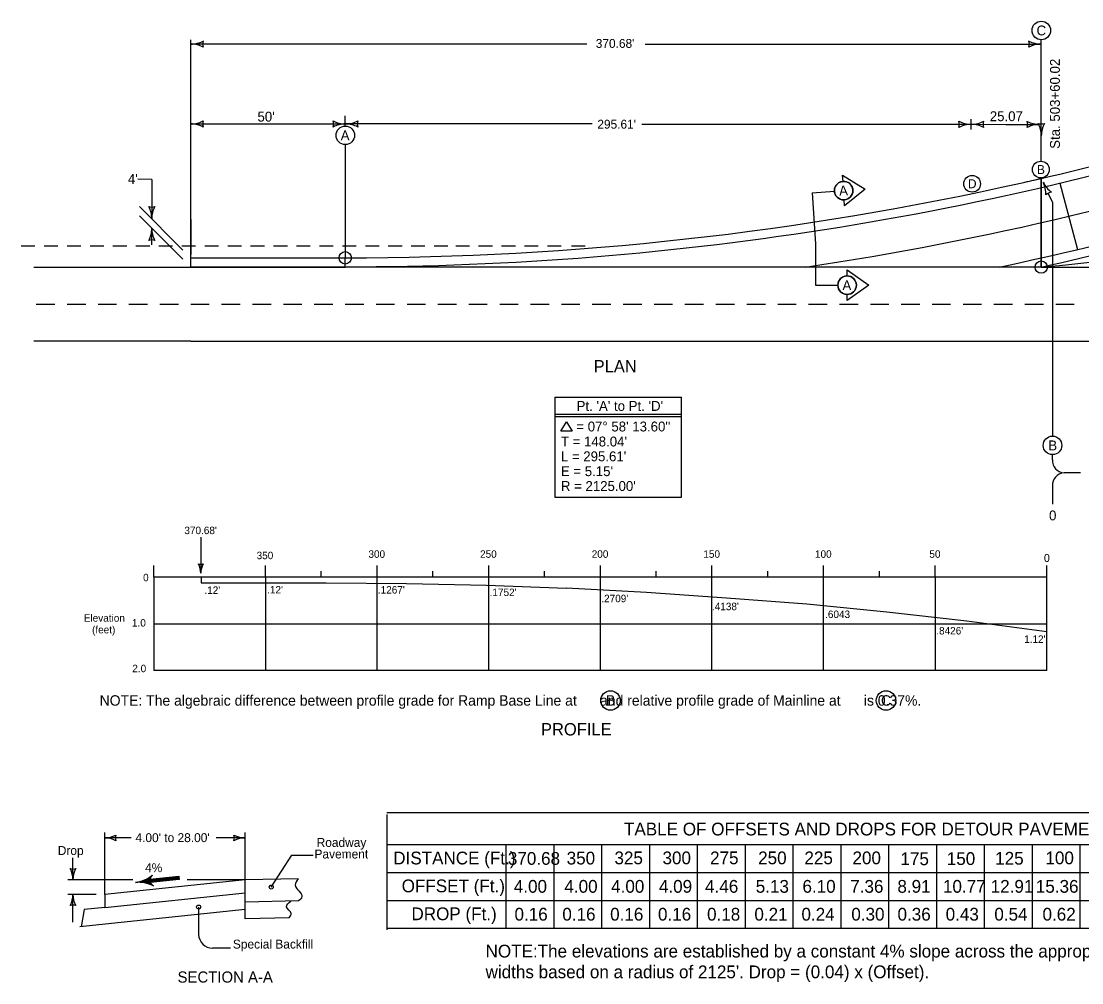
# Model space of a CAD drawing. Extents: x 10133 to 81668, y 4099 to 11018.
# Drawn here: x 10200 to 12089, y 4167 to 5879 of the extents above; entities that cross this region are included whole.
import ezdxf

# ---------------------------------------------------------------- set-up
doc = ezdxf.new("R2010")
doc.units = 0
for name, color, linetype in [('Default', 7, 'Continuous'), ('dsnCellElements', 7, 'Continuous'), ('Level 10', 7, 'Continuous'), ('Level 12', 7, 'Continuous'), ('Level 4', 7, 'Continuous'), ('Level 5', 7, 'Continuous'), ('SheetAddendum', 7, 'Continuous'), ('ShtPlotIdentification', 7, 'Continuous')]:
    doc.layers.add(name, color=color, linetype=linetype)

msp = doc.modelspace()

# ---------------------------------------------------------------- linework, layer by layer
at = {"layer": 'Default'}
for p, q in [((12016.5, 5441.5), (12016.5, 5599.5)), ((12016.5, 5599.5), (12016.5, 5441.5)), ((12049.8, 5590.9), (12080.7, 5472.7)), ((10488, 5471.9), (10410.7, 5549.2)), ((10488, 5455.4), (10410.7, 5532.7)), ((12016.5, 5441.5), (10501.9, 5441.5)), ((12016.5, 5441.5), (10501.9, 5441.5)), ((10776.9, 5441.5), (10776.9, 5458))]:
    msp.add_line(p, q, dxfattribs=at)
for points in [[(10501.9, 5441.5), (10501.9, 5458)], [(10501.9, 5458), (10776.9, 5458)]]:
    msp.add_lwpolyline(points, dxfattribs=at)
for centre, radius, start, end in [((10776.9, 10959.1), 5517, 270, 288.3725), ((10776.9, 10959.1), 5501.1, 282.6618, 288.3725), ((10776.9, 10959.1), 5578, 278.4444, 288.3725), ((10776.9, 10959.1), 5501.1, 270, 282.6618), ((10776.9, 10959.1), 5501.1, 270, 282.6618), ((10776.9, 10959.1), 5639.1, 281.9188, 288.3725), ((10776.9, 10959.1), 5501.1, 282.6618, 283.0225), ((10776.9, 10959.1), 5655.1, 282.6618, 288.3725), ((11515.8, 10985.3), 5566.3, 275.1605, 280.5457)]:
    msp.add_arc(centre, radius, start, end, dxfattribs=at)
at = {"layer": 'dsnCellElements'}
for p, q in [((12425.9, 4469.7), (10851.2, 4469.7)), ((10851.2, 4467.2), (10851.2, 4261.4)), ((12425.9, 4412.9), (10851.2, 4412.9)), ((11063.2, 4412.9), (11063.2, 4263.9)), ((11148.4, 4412.9), (11148.4, 4412.9)), ((11148.4, 4412.9), (11148.4, 4263.9)), ((11148.6, 4412.9), (11148.6, 4412.9)), ((11148.8, 4412.9), (11148.8, 4412.9)), ((11149.1, 4412.9), (11149.1, 4412.9)), ((11233.6, 4412.9), (11233.6, 4263.9)), ((11233.6, 4412.9), (11233.6, 4412.9)), ((11233.6, 4412.9), (11233.6, 4263.9)), ((11233.8, 4412.9), (11233.8, 4412.9)), ((11234, 4412.9), (11234, 4412.9)), ((11234.2, 4412.9), (11234.2, 4412.9)), ((11318.7, 4412.9), (11318.7, 4263.9)), ((11403.9, 4412.9), (11403.9, 4263.9)), ((11489.1, 4412.9), (11489.1, 4263.9)), ((11574.2, 4412.9), (11574.2, 4263.9)), ((11659.4, 4412.9), (11659.4, 4263.9)), ((11744.6, 4412.9), (11744.6, 4263.9)), ((11829.7, 4412.9), (11829.7, 4263.9)), ((11914.9, 4412.9), (11914.9, 4263.9)), ((12000.1, 4412.9), (12000.1, 4263.9)), ((12085.3, 4412.9), (12085.3, 4263.9)), ((12425.9, 4363.2), (10851.2, 4363.2)), ((12425.9, 4313.5), (10851.2, 4313.5)), ((12425.9, 4263.9), (10851.2, 4263.9))]:
    msp.add_line(p, q, dxfattribs=at)
at = {"layer": 'Level 10'}
for p, q in [((12036.5, 5557.3), (12029, 5573.1)), ((12036.5, 5557.3), (12036.5, 5140.6)), ((11150, 5209.9), (11150, 5031.8)), ((11150, 5209.9), (11375.5, 5209.9)), ((11375.5, 5031.8), (11375.5, 5209.9)), ((11150, 5179.9), (11375.5, 5179.9)), ((11150, 5175.7), (11375.5, 5175.7)), ((11161, 5149.4), (11170.9, 5165.9)), ((11170.9, 5165.9), (11180.8, 5149.4)), ((11180.8, 5149.4), (11161, 5149.4)), ((12036.5, 5098.4), (12036.5, 5107.6)), ((12086.5, 5075.2), (12057, 5075.2)), ((12036.5, 5052), (12036.5, 5019.3)), ((11150, 5031.8), (11375.5, 5031.8)), ((10348.6, 4324.7), (10348.6, 4434.9)), ((10598.7, 4350.8), (10598.7, 4434.9)), ((10515.9, 4302.2), (10515.9, 4253.8)), ((10572.4, 4229), (10540.7, 4229))]:
    msp.add_line(p, q, dxfattribs=at)
for centre, radius in [((12016.5, 5862.8), 16.5), ((10777.1, 5676.1), 16.5), ((12015.7, 5615.2), 14.9), ((11893.3, 5589.9), 14.9), ((10776.9, 5458), 11), ((12016.5, 5441.5), 11), ((12036.5, 5124.1), 16.5)]:
    msp.add_circle(centre, radius, dxfattribs=at)
for centre, radius, start, end in [((12016.5, 5714.6), 18.1, 252.2666, 287.7334), ((11969.7, 5675.4), 46.8, 0, 28.0725), ((12063.3, 5675.4), 46.8, 151.9275, 180), ((11977.3, 5572.1), 47.3, 357.3748, 25.4473), ((12062.8, 5612.8), 47.3, 205.4473, 233.5198), ((12037.1, 5556.6), 18.3, 97.714, 133.1807), ((10432.5, 5566.6), 18.1, 252.2666, 287.7334), ((10385.7, 5527.4), 46.8, 0, 28.0725), ((10479.2, 5527.4), 46.8, 151.9275, 180), ((10385.7, 5510.9), 46.8, 331.9275, 0), ((10479.2, 5510.9), 46.8, 180, 208.0725), ((10432.5, 5471.7), 18.1, 72.2667, 107.7334), ((12058.5, 5097.1), 22, 176.7081, 265.9437), ((12058.5, 5053.3), 22, 94.0563, 183.2919), ((10540.7, 4253.8), 24.8, 180, 270)]:
    msp.add_arc(centre, radius, start, end, dxfattribs=at)
for centre, major_axis, start_param, end_param in [((10519.7, 4926), (0, -13.6), 5.97368, 6.592691), ((10485.9, 4896.4), (0, 35.3), 4.712389, 5.202346), ((10553.5, 4896.4), (0, -35.3), 4.222432, 4.712389)]:
    msp.add_ellipse(centre, major_axis=major_axis, ratio=0.956827, start_param=start_param, end_param=end_param, dxfattribs=at)
at = {"layer": 'Level 12'}
for centre in [(10645.2, 4337.8), (10515.9, 4302.2)]:
    msp.add_circle(centre, 3.52, dxfattribs=at)
at = {"layer": 'Level 4'}
for p, q in [((11608.5, 5574), (11648, 5576.6)), ((11608.5, 5574), (11614.6, 5483.1)), ((11614.6, 5483.1), (11614.6, 5409.3)), ((11614.6, 5409.3), (11654.2, 5409.3))]:
    msp.add_line(p, q, dxfattribs=at)
for points in [[(11663.4, 5594.2), (11662.7, 5605.1), (11702.9, 5580.3), (11666.3, 5550.3), (11665.6, 5561.2)], [(11663.4, 5594.2), (11663.4, 5594.2), (11663.4, 5594.2)], [(11670.7, 5425.8), (11670.7, 5436.8), (11709.2, 5409.3), (11670.7, 5381.8), (11670.7, 5392.8)], [(11670.7, 5425.8), (11670.7, 5425.8), (11670.7, 5425.8)]]:
    msp.add_lwpolyline(points, dxfattribs=at)
for centre, radius in [((11664.5, 5577.7), 16.5), ((11670.7, 5409.3), 16.5), ((11249.3, 4669.9), 17.4), ((11740, 4669.9), 17.4)]:
    msp.add_circle(centre, radius, dxfattribs=at)
for centre, start, end in [((11664.5, 5577.7), 93.8133, 273.815), ((11664.5, 5577.7), 273.815, 93.8133), ((11670.7, 5409.3), 89.9992, 270.0008), ((11670.7, 5409.3), 270.0008, 89.9992)]:
    msp.add_arc(centre, 16.5, start, end, dxfattribs=at)
at = {"layer": 'Level 5'}
for p, q in [((10200, 5479.6), (10224.5, 5479.6)), ((10240.8, 5479.6), (10265.3, 5479.6)), ((10281.7, 5479.6), (10306.2, 5479.6)), ((10281.7, 5479.6), (10306.2, 5479.6)), ((10322.5, 5479.6), (10347, 5479.6)), ((10322.5, 5479.6), (10347, 5479.6)), ((10363.4, 5479.6), (10387.9, 5479.6)), ((10404.2, 5479.6), (10428.8, 5479.6)), ((10445.1, 5479.6), (10469.6, 5479.6)), ((10486, 5479.6), (10510.5, 5479.6)), ((10526.8, 5479.6), (10551.3, 5479.6)), ((10567.7, 5479.6), (10592.2, 5479.6)), ((10608.5, 5479.6), (10633, 5479.6)), ((10649.4, 5479.6), (10673.9, 5479.6)), ((10690.2, 5479.6), (10714.8, 5479.6)), ((10731.1, 5479.6), (10755.6, 5479.6)), ((10772, 5479.6), (10796.5, 5479.6)), ((10812.8, 5479.6), (10837.3, 5479.6)), ((10853.7, 5479.6), (10878.2, 5479.6)), ((10894.5, 5479.6), (10919, 5479.6)), ((10935.4, 5479.6), (10959.9, 5479.6)), ((10973.7, 5479.4), (10998.2, 5479.4)), ((11014.5, 5479.4), (11039, 5479.4)), ((11055.4, 5479.4), (11079.9, 5479.4)), ((11096.2, 5479.4), (11120.7, 5479.4)), ((11137.1, 5479.4), (11161.6, 5479.4)), ((11179.9, 5479.3), (11204.4, 5479.3)), ((10222.4, 5441.5), (10776.9, 5441.5)), ((12032, 5441.5), (12511.2, 5441.5)), ((10226.8, 5375.5), (10259.8, 5375.5)), ((10281.8, 5375.5), (10314.8, 5375.5)), ((10336.8, 5375.5), (10369.9, 5375.5)), ((10391.9, 5375.5), (10424.9, 5375.5)), ((10446.9, 5375.5), (10479.9, 5375.5)), ((10501.9, 5375.5), (10534.9, 5375.5)), ((10556.9, 5375.5), (10589.9, 5375.5)), ((10611.9, 5375.5), (10644.9, 5375.5)), ((10666.9, 5375.5), (10699.9, 5375.5)), ((10721.9, 5375.5), (10754.9, 5375.5)), ((10776.9, 5375.5), (10809.9, 5375.5)), ((10831.9, 5375.5), (10864.9, 5375.5)), ((10887, 5375.5), (10920, 5375.5)), ((10942, 5375.5), (10975, 5375.5)), ((10997, 5375.5), (11030, 5375.5)), ((11052, 5375.5), (11085, 5375.5)), ((11107, 5375.5), (11140, 5375.5)), ((11162, 5375.5), (11195, 5375.5)), ((11217, 5375.5), (11250, 5375.5)), ((11272, 5375.5), (11305, 5375.5)), ((11327, 5375.5), (11360, 5375.5)), ((11382, 5375.5), (11415.1, 5375.5)), ((11437.1, 5375.5), (11470.1, 5375.5)), ((11492.1, 5375.5), (11525.1, 5375.5)), ((11547.1, 5375.5), (11580.1, 5375.5)), ((11602.1, 5375.5), (11635.1, 5375.5)), ((11657.1, 5375.5), (11690.1, 5375.5)), ((11712.1, 5375.5), (11745.1, 5375.5)), ((11767.1, 5375.5), (11800.1, 5375.5)), ((11822.1, 5375.5), (11855.1, 5375.5)), ((11877.1, 5375.5), (11910.2, 5375.5)), ((11932.2, 5375.5), (11965.2, 5375.5)), ((11987.2, 5375.5), (12020.2, 5375.5)), ((12042.2, 5375.5), (12075.2, 5375.5)), ((10501.9, 5309.5), (10222.4, 5309.5)), ((10501.9, 5309.5), (12511, 5309.5)), ((10519.7, 4960.9), (10519.7, 4896.4)), ((10436.2, 4889.6), (10436.2, 4910.3)), ((10635, 4889.6), (10635, 4910.3)), ((10734.4, 4889.6), (10734.4, 4899.9)), ((10833.8, 4723.3), (10833.8, 4910.3)), ((10933.2, 4889.6), (10933.2, 4899.9)), ((11032.6, 4723.3), (11032.6, 4910.3)), ((11132, 4889.6), (11132, 4899.9)), ((11231.4, 4723.3), (11231.4, 4910.3)), ((11330.8, 4889.6), (11330.8, 4899.9)), ((11430.1, 4723.3), (11430.1, 4910.3)), ((11529.5, 4889.6), (11529.5, 4899.9)), ((11628.9, 4723.3), (11628.9, 4910.3)), ((11728.3, 4889.6), (11728.3, 4899.9)), ((11827.7, 4889.6), (11827.7, 4910.3)), ((12026.5, 4723.3), (12026.5, 4910.3)), ((12026.5, 4889.6), (10436.2, 4889.6)), ((10436.2, 4889.6), (10436.2, 4723.3)), ((10520.3, 4889.5), (10520.3, 4879.2)), ((10520.3, 4879.2), (10600.6, 4879.2)), ((10600.6, 4879.2), (10743.2, 4879.2)), ((10635, 4889.6), (10635, 4723.3)), ((10743.2, 4879.2), (10885.8, 4878.4)), ((10885.8, 4878.4), (11028.4, 4875)), ((11028.4, 4875), (11171, 4869.9)), ((11827.7, 4889.6), (11827.7, 4723.3)), ((11313.6, 4862.3), (11171, 4869.9)), ((11456.2, 4852.2), (11313.6, 4862.3)), ((11598.8, 4841.3), (11456.2, 4852.2)), ((11741.3, 4826.9), (11598.8, 4841.3)), ((11883.9, 4810.9), (11741.3, 4826.9)), ((10436.2, 4806.4), (12026.5, 4806.4)), ((12026.5, 4792.4), (11883.9, 4810.9)), ((12026.5, 4723.3), (10436.2, 4723.3)), ((10645.2, 4337.8), (10681.7, 4394.4)), ((10681.7, 4394.4), (10719.6, 4394.4)), ((10598.7, 4350.8), (10348.6, 4324.7)), ((10694, 4352.7), (10598.7, 4350.8)), ((10598.7, 4281.3), (10598.7, 4350.8)), ((10348.6, 4301.5), (10598.7, 4327.6)), ((10348.6, 4324.7), (10348.6, 4301.5)), ((10694, 4313), (10599.5, 4311.1)), ((10598.7, 4297.7), (10304.3, 4266.9)), ((10311.8, 4297.6), (10307, 4267.2)), ((10348.6, 4301.5), (10311.8, 4297.6)), ((10677, 4282.8), (10600.1, 4281.3))]:
    msp.add_line(p, q, dxfattribs=at)
msp.add_lwpolyline([(10501.9, 5458), (10776.9, 5458)], dxfattribs=at)
msp.add_lwpolyline([(10598.7, 4350.8), (10348.6, 4324.7), (10348.6, 4301.5), (10598.7, 4327.6)], close=True, dxfattribs=at)
for points in [[(10694, 4352.7), (10687.9, 4341.1), (10699.9, 4320.9), (10694, 4313)], [(10677, 4282.8), (10680.8, 4290.8), (10672.6, 4302.8), (10680.2, 4312.7)]]:
    msp.add_spline(points, degree=3, dxfattribs=at)
at = {"layer": 'SheetAddendum'}
for p, q in [((10501.9, 5441.5), (10501.9, 5846.3)), ((11207, 5838.6), (10501.9, 5838.6)), ((11311.3, 5838.6), (12016.5, 5838.6)), ((12016.5, 5630.1), (12016.5, 5846.3)), ((10777.1, 5692.6), (10777.1, 5711.1)), ((11891.8, 5686.6), (11891.8, 5705.1)), ((10502.2, 5696.3), (10659.6, 5696.3)), ((10659.6, 5696.3), (10777.3, 5696.3)), ((11216.8, 5696.7), (10777.3, 5696.3)), ((11305.2, 5695.7), (11889.2, 5695.7)), ((11891.9, 5695.7), (11953.5, 5695.6)), ((11953.4, 5695.6), (12013.6, 5695.6)), ((10777.3, 5458), (10777.3, 5659.6)), ((10432.5, 5597.6), (10407.5, 5597.9)), ((10432.5, 5597.6), (10432.5, 5527.4)), ((12016.5, 5519.9), (12016.5, 5600.4)), ((10501.9, 5526.1), (10501.9, 5464.2)), ((10432.5, 5480.9), (10432.5, 5510.9)), ((10396, 4425.3), (10348.6, 4425.3)), ((10598.7, 4425.3), (10547, 4425.3)), ((10292.1, 4350.8), (10292.1, 4389.8)), ((10398.7, 4350.8), (10282.9, 4350.8)), ((10429.3, 4351.9), (10429.3, 4351.9)), ((10429.5, 4348.8), (10481.1, 4354.2)), ((10429.9, 4345.8), (10429.9, 4345.8)), ((10598.4, 4350.8), (10495.4, 4350.8)), ((10333.2, 4324.7), (10282.9, 4324.7)), ((10292.1, 4275.3), (10292.1, 4324.7))]:
    msp.add_line(p, q, dxfattribs=at)
for points in [[(10430.3, 4355.7), (10428.5, 4352), (10428.7, 4346.8), (10431.1, 4342.5), (10423.1, 4344.9), (10414, 4346.6), (10411.4, 4346.9), (10417.7, 4348.9), (10426.7, 4353.1), (10429.3, 4354.9), (10429.4, 4343.8), (10415.2, 4347.1), (10428.2, 4352.6), (10428.5, 4345), (10418.7, 4347.5), (10427.1, 4350.6), (10428, 4346.2), (10421.8, 4347.6), (10426.2, 4349.4), (10426.7, 4347.3), (10424.4, 4347.7)], [(10429.3, 4351.7), (10480.8, 4357.1), (10481.4, 4351.2), (10429.9, 4345.8), (10429.6, 4350.9), (10480.2, 4356.4), (10480.6, 4351.7), (10431, 4346.7), (10430.5, 4350.2), (10479.6, 4355.5), (10479.8, 4352.4), (10431.6, 4347.3), (10431.2, 4349.5), (10479.1, 4354.8), (10479.2, 4353), (10432.1, 4348.2)]]:
    msp.add_lwpolyline(points, dxfattribs=at)
for centre, radius, start, end in [((10501.9, 5885.3), 46.8, 270, 298.0725), ((10501.9, 5791.8), 46.8, 61.9275, 90), ((10541.1, 5838.6), 18.1, 162.2666, 197.7334), ((11977.3, 5838.6), 18.1, 342.2666, 17.7333), ((12016.5, 5885.3), 46.8, 241.9275, 270), ((12016.5, 5791.8), 46.8, 90, 118.0725), ((10502.2, 5743.1), 46.8, 270, 298.0725), ((10502.2, 5649.6), 46.8, 61.9275, 90), ((10541.4, 5696.3), 18.1, 162.2666, 197.7334), ((10738.1, 5696.3), 18.1, 342.2667, 17.7334), ((10777.3, 5743.1), 46.8, 241.9275, 270), ((10777.3, 5649.6), 46.8, 90, 118.0725), ((10777.3, 5743.1), 46.8, 270, 298.0725), ((10777.3, 5649.6), 46.8, 61.9275, 90), ((10816.5, 5696.3), 18.1, 162.2666, 197.7334), ((11852.6, 5695.7), 18.1, 342.2666, 17.7333), ((11891.9, 5742.5), 46.8, 241.9275, 270), ((11891.9, 5648.9), 46.8, 90, 118.0725), ((11891.9, 5742.5), 46.8, 270, 298.0725), ((11891.9, 5648.9), 46.8, 61.9275, 90), ((11931.1, 5695.7), 18.1, 162.2666, 197.7334), ((11974.3, 5695.6), 18.1, 342.2667, 17.7334), ((12013.6, 5742.3), 46.8, 241.9275, 270), ((12013.6, 5648.8), 46.8, 90, 118.0725), ((10348.6, 4467.5), 42.2, 270, 298.0725), ((10348.6, 4383.1), 42.2, 61.9275, 90), ((10384, 4425.3), 16.3, 162.2666, 197.7334), ((10563.3, 4425.3), 16.3, 342.2667, 17.7334), ((10598.7, 4467.5), 42.2, 241.9275, 270), ((10598.7, 4383.1), 42.2, 90, 118.0725), ((10292.1, 4386.2), 16.3, 252.2667, 287.7334), ((10249.9, 4350.8), 42.2, 0, 28.0725), ((10334.3, 4350.8), 42.2, 151.9275, 180), ((10249.9, 4324.7), 42.2, 331.9275, 0), ((10334.3, 4324.7), 42.2, 180, 208.0725), ((10292.1, 4289.3), 16.3, 72.2666, 107.7334)]:
    msp.add_arc(centre, radius, start, end, dxfattribs=at)
for centre, major_axis, start_param, end_param in [((10394.8, 4409.5), (6.7, -63.7), 0.029395, 0.553518), ((10408.1, 4282.2), (6.7, -63.7), 2.588074, 3.112197), ((10440.2, 4349.9), (-1.2, 11.1), 0.553526, 2.588067)]:
    msp.add_ellipse(centre, major_axis=major_axis, ratio=0.985299, start_param=start_param, end_param=end_param, dxfattribs=at)
at = {"layer": 'ShtPlotIdentification'}
for p, q in [((10501.9, 5441.5), (10501.9, 5458)), ((12016.5, 5441.5), (12032, 5441.5))]:
    msp.add_line(p, q, dxfattribs=at)

# ---------------------------------------------------------------- texts
at = {"layer": 'dsnCellElements'}
for s, height, p in [('TABLE OF OFFSETS AND DROPS FOR DETOUR PAVEMENT', 22.712, (11273.4, 4429.7)), ('DISTANCE (Ft.)', 22.712, (10862.5, 4378.1)), ('350', 22.71, (11171.3, 4378)), ('325', 22.71, (11256.4, 4378.4)), ('300', 22.71, (11342, 4378.4)), ('275', 22.71, (11426.7, 4378.4)), ('250', 22.71, (11512.3, 4378.4)), ('225', 22.71, (11594.7, 4378.4)), ('200', 22.71, (11680.3, 4378.4)), ('125', 22.71, (11934.4, 4377.7)), ('100', 22.71, (12023.9, 4378.4)), ('370.68', 22.71, (11066.6, 4377.4)), ('175', 22.71, (11765.7, 4376.8)), ('150', 22.71, (11848.2, 4377.1)), ('OFFSET (Ft.)', 22.712, (10877.5, 4328.5)), ('4.00', 22.71, (11077.2, 4327.7)), ('4.00', 22.71, (11167.3, 4327.7)), ('4.00', 22.71, (11250.5, 4327.7)), ('4.09', 22.71, (11335.6, 4327.7)), ('4.46', 22.71, (11417.8, 4327.7)), ('5.13', 22.71, (11508, 4327.7)), ('6.10', 22.71, (11591.2, 4327.7)), ('7.36', 22.71, (11676.3, 4327.7)), ('8.91', 22.71, (11760.3, 4327.7)), ('10.77', 22.71, (11841.4, 4327.7)), ('12.91', 22.71, (11926.4, 4327.7)), ('15.36', 22.71, (12006.8, 4327.7)), ('DROP (Ft.)', 22.71, (10894.9, 4278.8)), ('0.16', 22.71, (11078.4, 4278.1)), ('0.16', 22.71, (11163.6, 4278.1)), ('0.16', 22.71, (11248.7, 4278.1)), ('0.16', 22.71, (11333.9, 4278.1)), ('0.18', 22.71, (11421.3, 4278.1)), ('0.21', 22.71, (11505.6, 4278.1)), ('0.24', 22.71, (11589.4, 4278.1)), ('0.30', 22.71, (11678.2, 4278.1)), ('0.36', 22.71, (11760.5, 4278.1)), ('0.43', 22.71, (11846.2, 4278.1)), ('0.54', 22.71, (11932.9, 4278.1)), ('0.62', 22.71, (12018.7, 4278.1))]:
    msp.add_text(s, height=height, dxfattribs=at).set_placement(p)
at = {"layer": 'Level 10'}
for s, height, p in [('C', 17.6, (12008.1, 5854)), ("370.68'", 15.84, (11223.1, 5831.8)), ("50'", 17.6, (10620.7, 5700.5)), ("295.61'", 15.84, (11225.9, 5688)), ('25.07', 17.6, (11924.8, 5701.3)), ('A', 17.6, (10768.9, 5667.3)), ('B', 15.8, (12008.9, 5607.3)), ('D', 15.8, (11885.9, 5582)), ('PLAN', 22, (11219.3, 5254)), ("Pt. 'A' to Pt. 'D'", 17.603, (11189, 5185.5)), ("= 07° 58' 13.60''", 17.603, (11188.5, 5148.9)), ("T = 148.04'", 17.603, (11161, 5122.2)), ('B', 17.6, (12029, 5115.3)), ("L = 295.61'", 17.603, (11161, 5095.8)), ("E = 5.15'", 17.6, (11161, 5069.4)), ("R = 2125.00'", 17.603, (11161, 5043)), ('0', 17.6, (12030.3, 4990.6)), ("370.68'", 13.3, (10490.5, 4966.1)), ('350', 13.3, (10619.2, 4921.5)), ('300', 13.3, (10818.3, 4924)), ('250', 13.3, (11017.1, 4924)), ('200', 13.3, (11215.9, 4924)), ('150', 13.3, (11414.7, 4924)), ('100', 13.3, (11613.5, 4924)), ('50', 13.3, (11817.2, 4924)), ('0', 14.2, (12021.2, 4916.6)), ('0', 13.3, (10417, 4882.2)), (".12'", 13.3, (10526.2, 4859.7)), (".12'", 13.3, (10637.9, 4860.5)), (".1267'", 13.3, (10835.1, 4860.3)), (".1752'", 13.3, (11034.1, 4855.9)), (".2709'", 13.3, (11233, 4844.9)), (".4138'", 13.3, (11430, 4830.7)), ('Elevation', 13.3, (10311.4, 4810.2)), ('.6043', 13.3, (11631.5, 4816.8)), ('(feet)', 13.3, (10326.1, 4789.4)), ('1.0', 13.3, (10397.2, 4801.6)), (".8426'", 13.3, (11829.5, 4787.5)), ("1.12'", 13.3, (11985.9, 4772.5)), ('2.0', 13.3, (10397.8, 4720.3)), ('NOTE: The algebraic difference between profile grade for Ramp Base Line at      and relative profile grade of Mainline at      is 0.37%. ', 18.5883, (10339.6, 4660.7)), ('B', 18.6, (11241.3, 4660.7)), ('C', 18.6, (11731.1, 4660.7)), ('PROFILE', 22, (11125.5, 4607.7)), ('Roadway', 15.89, (10726, 4409.3)), ('Pavement', 15.89, (10722.2, 4388.7)), ('Special Backfill', 15.889, (10576.9, 4228.3)), ('NOTE:The elevations are established by a constant 4% slope across the appropriate detour', 22.712, (11026.9, 4212.4)), ("widths based on a radius of 2125'. Drop = (0.04) x (Offset).", 22.712, (11026.9, 4175.5))]:
    msp.add_text(s, height=height, dxfattribs=at).set_placement(p)
msp.add_text('Sta. 503+60.02', height=17.603, rotation=90, dxfattribs=at).set_placement((12049.6, 5652.1))
at = {"layer": 'Level 4'}
msp.add_text('A', height=17.6, rotation=3.8141, dxfattribs=at).set_placement((11656.9, 5568.4))
for s, height, p in [('A', 17.6, (11662.4, 5400.5)), ('SECTION A-A', 19.862, (10478.4, 4167.7))]:
    msp.add_text(s, height=height, dxfattribs=at).set_placement(p)
at = {"layer": 'SheetAddendum'}
for s, height, p in [("4'", 17.6, (10389.9, 5589.6)), ("4.00' to 28.00'", 15.889, (10403.4, 4417.8)), ('Drop', 15.89, (10265.1, 4394.9)), ('4%', 15.89, (10420.5, 4364.3))]:
    msp.add_text(s, height=height, dxfattribs=at).set_placement(p)

doc.saveas('drawing.dxf')
